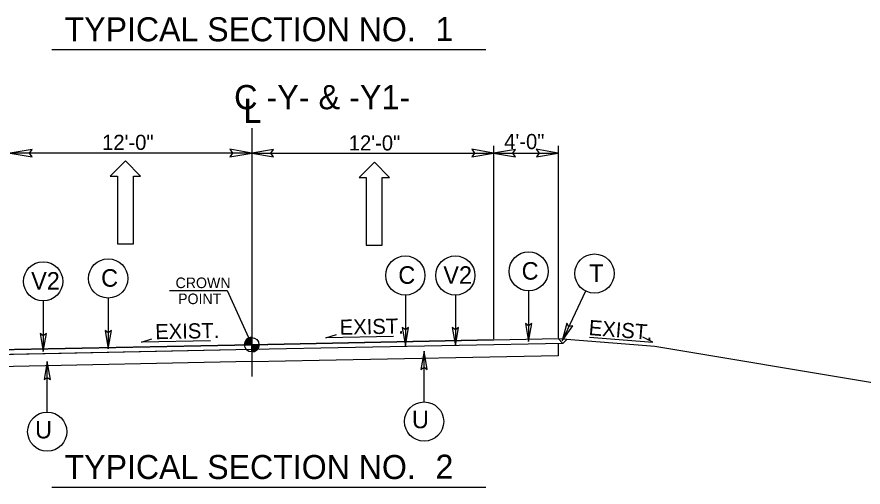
# Model space of a CAD drawing. Extents: x 2137858 to 2138172, y 2136084 to 2136289.
# Drawn here: x 2137980.7 to 2138065.4, y 2136135 to 2136182 of the extents above; entities that cross this region are included whole.
import ezdxf

# ---------------------------------------------------------------- set-up
doc = ezdxf.new("R2010")
doc.units = 0
for name, color, linetype in [('Old_Level_1', 7, 'Continuous'), ('Old_Level_11', 7, 'Continuous'), ('Old_Level_2', 7, 'Continuous'), ('Old_Level_20', 7, 'Continuous'), ('Old_Level_3', 7, 'Continuous'), ('Old_Level_4', 7, 'Continuous'), ('Typical Grade Point Symbol CELL', 7, 'Continuous')]:
    doc.layers.add(name, color=color, linetype=linetype)

msp = doc.modelspace()

# ---------------------------------------------------------------- linework, layer by layer
at = {"layer": 'Old_Level_1'}
for p, q in [((2137984.23, 2136178.793), (2138027.672, 2136178.793)), ((2138034.889, 2136149.88), (2138044.569, 2136149.106)), ((2138038.012, 2136150.024), (2138044.36, 2136149.517)), ((2138044.36, 2136149.517), (2138043.375, 2136150.009)), ((2138004.245, 2136148.772), (2137973.125, 2136148.15)), ((2138035.374, 2136149.395), (2138004.245, 2136148.772)), ((2138034.889, 2136149.385), (2138034.889, 2136148.185)), ((2138044.569, 2136149.106), (2138066.349, 2136145.476)), ((2138010.974, 2136147.705), (2138034.889, 2136148.185)), ((2138004.236, 2136147.57), (2137973.125, 2136146.95)), ((2138004.236, 2136147.57), (2138010.974, 2136147.705)), ((2137984.23, 2136135.034), (2138027.672, 2136135.034))]:
    msp.add_line(p, q, dxfattribs=at)
for points in [[(2138018.413, 2136150.094), (2138011.664, 2136149.954), (2138012.701, 2136150.3)], [(2138000.101, 2136149.652), (2137993.208, 2136149.509), (2137994.245, 2136149.856)]]:
    msp.add_lwpolyline(points, dxfattribs=at)
msp.add_lwpolyline([(2138004.236, 2136149.266), (2138034.889, 2136149.88), (2138035.374, 2136149.395), (2138004.245, 2136148.772), (2137973.629, 2136148.16), (2137973.125, 2136148.15), (2137973.629, 2136148.655)], close=True, dxfattribs=at)
at = {"layer": 'Old_Level_11'}
for p, q in [((2138004.236, 2136170.908), (2138004.236, 2136167.727)), ((2138028.436, 2136169.144), (2138028.436, 2136149.852)), ((2138034.889, 2136169.144), (2138034.889, 2136149.95)), ((2138004.236, 2136168.422), (2137980.082, 2136168.422)), ((2138004.236, 2136168.619), (2138004.236, 2136146.079)), ((2138004.236, 2136168.42), (2138028.436, 2136168.42)), ((2138028.436, 2136168.42), (2138034.889, 2136168.42)), ((2138031.941, 2136154.638), (2138031.941, 2136149.572)), ((2138037.64, 2136154.63), (2138035.283, 2136149.638)), ((2137989.872, 2136153.931), (2137989.872, 2136148.865)), ((2138019.605, 2136154.224), (2138019.605, 2136149.158)), ((2138024.607, 2136154.224), (2138024.607, 2136149.158)), ((2137983.371, 2136153.638), (2137983.371, 2136148.573)), ((2138021.482, 2136143.544), (2138021.482, 2136148.61)), ((2137983.781, 2136142.531), (2137983.781, 2136147.597))]:
    msp.add_line(p, q, dxfattribs=at)
for points in [[(2137982.26, 2136168.796), (2137980.082, 2136168.422), (2137982.273, 2136168.035), (2137981.994, 2136168.422)], [(2138002.058, 2136168.048), (2138004.236, 2136168.422), (2138002.045, 2136168.809), (2138002.324, 2136168.422)], [(2138006.414, 2136168.796), (2138004.236, 2136168.42), (2138006.425, 2136168.033), (2138006.147, 2136168.42)], [(2138026.258, 2136168.044), (2138028.436, 2136168.42), (2138026.246, 2136168.807), (2138026.524, 2136168.42)], [(2138030.614, 2136168.796), (2138028.436, 2136168.42), (2138030.626, 2136168.033), (2138030.347, 2136168.42)], [(2138032.711, 2136168.044), (2138034.889, 2136168.42), (2138032.698, 2136168.807), (2138032.977, 2136168.42)], [(2138031.628, 2136151.387), (2138031.941, 2136149.572), (2138032.264, 2136151.397), (2138031.941, 2136151.166)], [(2138035.771, 2136151.414), (2138035.283, 2136149.638), (2138036.351, 2136151.152), (2138035.961, 2136151.081)], [(2137983.058, 2136150.388), (2137983.371, 2136148.573), (2137983.693, 2136150.397), (2137983.371, 2136150.167)], [(2137989.559, 2136150.68), (2137989.872, 2136148.865), (2137990.195, 2136150.69), (2137989.872, 2136150.459)], [(2138019.292, 2136150.973), (2138019.605, 2136149.158), (2138019.927, 2136150.983), (2138019.605, 2136150.752)], [(2138024.294, 2136150.973), (2138024.607, 2136149.158), (2138024.93, 2136150.983), (2138024.607, 2136150.752)], [(2138021.795, 2136146.795), (2138021.482, 2136148.61), (2138021.159, 2136146.786), (2138021.482, 2136147.016)], [(2137984.094, 2136145.782), (2137983.781, 2136147.597), (2137983.458, 2136145.772), (2137983.781, 2136146.003)]]:
    msp.add_lwpolyline(points, close=True, dxfattribs=at)
for centre in [(2138019.605, 2136156.185), (2138024.608, 2136156.185), (2138031.942, 2136156.599), (2138038.527, 2136156.378), (2137983.371, 2136155.6), (2137989.873, 2136155.892), (2138021.48, 2136141.584), (2137983.779, 2136140.57)]:
    msp.add_circle(centre, 1.96, dxfattribs=at)
at = {"layer": 'Old_Level_2'}
for p, q in [((2138028.436, 2136149.751), (2138004.236, 2136149.267)), ((2138028.436, 2136149.751), (2138034.889, 2136149.88)), ((2138034.889, 2136149.88), (2138035.374, 2136149.395)), ((2138035.787, 2136149.808), (2138035.374, 2136149.395)), ((2138004.236, 2136149.266), (2137973.629, 2136148.655)), ((2138004.245, 2136148.772), (2138004.236, 2136149.266)), ((2138034.889, 2136148.652), (2138034.889, 2136148.159))]:
    msp.add_line(p, q, dxfattribs=at)
at = {"layer": 'Old_Level_3'}
for p, q in [((2137996.025, 2136154.67), (2138001.764, 2136154.67)), ((2138001.764, 2136154.67), (2138004.236, 2136149.266))]:
    msp.add_line(p, q, dxfattribs=at)
at = {"layer": 'Old_Level_4'}
for p, q in [((2137991.621, 2136167.635), (2137990.073, 2136166.11)), ((2137993.122, 2136166.11), (2137991.621, 2136167.635)), ((2138016.519, 2136167.503), (2138014.97, 2136165.978)), ((2138018.019, 2136165.978), (2138016.519, 2136167.503)), ((2137990.073, 2136166.11), (2137990.799, 2136166.11)), ((2137990.799, 2136166.11), (2137990.799, 2136159.334)), ((2137992.396, 2136159.334), (2137992.396, 2136166.11)), ((2137992.396, 2136166.11), (2137993.122, 2136166.11)), ((2138014.97, 2136165.978), (2138015.696, 2136165.978)), ((2138015.696, 2136165.978), (2138015.696, 2136159.202)), ((2138017.293, 2136159.202), (2138017.293, 2136165.978)), ((2138017.293, 2136165.978), (2138018.019, 2136165.978)), ((2137990.799, 2136159.334), (2137992.396, 2136159.334)), ((2138015.696, 2136159.202), (2138017.293, 2136159.202))]:
    msp.add_line(p, q, dxfattribs=at)
at = {"layer": 'Typical Grade Point Symbol CELL'}
for p, q in [((2138004.236, 2136149.266), (2138004.236, 2136149.992)), ((2138003.51, 2136149.266), (2138004.236, 2136149.266)), ((2138004.237, 2136148.54), (2138004.236, 2136149.266)), ((2138004.962, 2136149.266), (2138004.236, 2136149.266)), ((2138004.236, 2136149.266), (2138004.237, 2136148.54))]:
    msp.add_line(p, q, dxfattribs=at)
for points in [[(2138003.532, 2136149.443), (2138003.532, 2136149.266)], [(2138003.547, 2136149.493), (2138003.547, 2136149.266)], [(2138003.561, 2136149.533), (2138003.561, 2136149.266)], [(2138003.576, 2136149.567), (2138003.576, 2136149.266)], [(2138003.59, 2136149.598), (2138003.59, 2136149.266)], [(2138003.605, 2136149.624), (2138003.605, 2136149.266)], [(2138003.619, 2136149.648), (2138003.619, 2136149.266)], [(2138003.634, 2136149.671), (2138003.634, 2136149.266)], [(2138003.648, 2136149.692), (2138003.648, 2136149.266)], [(2138003.663, 2136149.711), (2138003.663, 2136149.266)], [(2138003.677, 2136149.729), (2138003.677, 2136149.266)], [(2138003.692, 2136149.746), (2138003.692, 2136149.266)], [(2138003.706, 2136149.763), (2138003.706, 2136149.266)], [(2138003.721, 2136149.777), (2138003.721, 2136149.266)], [(2138003.735, 2136149.792), (2138003.735, 2136149.266)], [(2138003.75, 2136149.805), (2138003.75, 2136149.266)], [(2138003.764, 2136149.817), (2138003.764, 2136149.266)], [(2138003.779, 2136149.83), (2138003.779, 2136149.266)], [(2138003.793, 2136149.842), (2138003.793, 2136149.266)], [(2138003.808, 2136149.851), (2138003.808, 2136149.266)], [(2138003.823, 2136149.863), (2138003.823, 2136149.266)], [(2138003.837, 2136149.872), (2138003.837, 2136149.266)], [(2138003.852, 2136149.882), (2138003.852, 2136149.266)], [(2138003.866, 2136149.89), (2138003.866, 2136149.266)], [(2138003.881, 2136149.898), (2138003.881, 2136149.266)], [(2138003.895, 2136149.906), (2138003.895, 2136149.266)], [(2138003.91, 2136149.914), (2138003.91, 2136149.266)], [(2138003.924, 2136149.921), (2138003.924, 2136149.266)], [(2138003.939, 2136149.927), (2138003.939, 2136149.266)], [(2138003.953, 2136149.934), (2138003.953, 2136149.266)], [(2138003.968, 2136149.94), (2138003.968, 2136149.266)], [(2138003.982, 2136149.946), (2138003.982, 2136149.266)], [(2138003.997, 2136149.951), (2138003.997, 2136149.266)], [(2138004.011, 2136149.956), (2138004.011, 2136149.266)], [(2138004.026, 2136149.961), (2138004.026, 2136149.266)], [(2138004.04, 2136149.964), (2138004.04, 2136149.266)], [(2138004.055, 2136149.969), (2138004.055, 2136149.266)], [(2138004.069, 2136149.972), (2138004.069, 2136149.266)], [(2138004.084, 2136149.976), (2138004.084, 2136149.266)], [(2138004.098, 2136149.979), (2138004.098, 2136149.266)], [(2138004.113, 2136149.982), (2138004.113, 2136149.266)], [(2138004.127, 2136149.984), (2138004.127, 2136149.266)], [(2138004.142, 2136149.985), (2138004.142, 2136149.266)], [(2138004.156, 2136149.987), (2138004.156, 2136149.266)], [(2138004.171, 2136149.988), (2138004.171, 2136149.266)], [(2138004.186, 2136149.99), (2138004.186, 2136149.266)], [(2138004.2, 2136149.99), (2138004.2, 2136149.266)], [(2138004.215, 2136149.992), (2138004.215, 2136149.266)], [(2138004.229, 2136149.992), (2138004.229, 2136149.992), (2138004.229, 2136149.266)], [(2138003.518, 2136149.369), (2138003.518, 2136149.266)], [(2138004.247, 2136149.266), (2138004.247, 2136148.54), (2138004.247, 2136148.54)], [(2138004.261, 2136149.266), (2138004.261, 2136148.54)], [(2138004.276, 2136149.266), (2138004.276, 2136148.541)], [(2138004.29, 2136149.266), (2138004.29, 2136148.541)], [(2138004.305, 2136149.266), (2138004.305, 2136148.543)], [(2138004.319, 2136149.266), (2138004.319, 2136148.544)], [(2138004.334, 2136149.266), (2138004.334, 2136148.546)], [(2138004.348, 2136149.266), (2138004.348, 2136148.549)], [(2138004.363, 2136149.266), (2138004.363, 2136148.551)], [(2138004.378, 2136149.266), (2138004.378, 2136148.554)], [(2138004.392, 2136149.266), (2138004.392, 2136148.557)], [(2138004.407, 2136149.266), (2138004.407, 2136148.561)], [(2138004.421, 2136149.266), (2138004.421, 2136148.564)], [(2138004.436, 2136149.266), (2138004.436, 2136148.569)], [(2138004.45, 2136149.266), (2138004.45, 2136148.572)], [(2138004.465, 2136149.266), (2138004.465, 2136148.577)], [(2138004.479, 2136149.266), (2138004.479, 2136148.582)], [(2138004.494, 2136149.266), (2138004.494, 2136148.586)], [(2138004.508, 2136149.266), (2138004.508, 2136148.593)], [(2138004.523, 2136149.266), (2138004.523, 2136148.599)], [(2138004.537, 2136149.266), (2138004.537, 2136148.606)], [(2138004.552, 2136149.266), (2138004.552, 2136148.612)], [(2138004.566, 2136149.266), (2138004.566, 2136148.619)], [(2138004.581, 2136149.266), (2138004.581, 2136148.627)], [(2138004.595, 2136149.266), (2138004.595, 2136148.635)], [(2138004.61, 2136149.266), (2138004.61, 2136148.643)], [(2138004.624, 2136149.266), (2138004.624, 2136148.653)], [(2138004.639, 2136149.266), (2138004.639, 2136148.662)], [(2138004.653, 2136149.266), (2138004.653, 2136148.672)], [(2138004.668, 2136149.266), (2138004.668, 2136148.682)], [(2138004.682, 2136149.266), (2138004.682, 2136148.693)], [(2138004.697, 2136149.266), (2138004.697, 2136148.704)], [(2138004.711, 2136149.266), (2138004.711, 2136148.717)], [(2138004.726, 2136149.266), (2138004.726, 2136148.73)], [(2138004.741, 2136149.266), (2138004.741, 2136148.743)], [(2138004.755, 2136149.266), (2138004.755, 2136148.757)], [(2138004.77, 2136149.266), (2138004.77, 2136148.774)], [(2138004.784, 2136149.266), (2138004.784, 2136148.79)], [(2138004.799, 2136149.266), (2138004.799, 2136148.807)], [(2138004.813, 2136149.266), (2138004.813, 2136148.825)], [(2138004.828, 2136149.266), (2138004.828, 2136148.845)], [(2138004.842, 2136149.266), (2138004.842, 2136148.866)], [(2138004.857, 2136149.266), (2138004.857, 2136148.888)], [(2138004.871, 2136149.266), (2138004.871, 2136148.914)], [(2138004.886, 2136149.266), (2138004.886, 2136148.941)], [(2138004.9, 2136149.266), (2138004.9, 2136148.972)], [(2138004.915, 2136149.266), (2138004.915, 2136149.006)], [(2138004.929, 2136149.266), (2138004.929, 2136149.049)], [(2138004.944, 2136149.266), (2138004.944, 2136149.101)], [(2138004.958, 2136149.266), (2138004.958, 2136149.187)]]:
    msp.add_lwpolyline(points, dxfattribs=at)
msp.add_circle((2138004.237, 2136149.266), 0.726, dxfattribs=at)
for start, end in [(90.00952, 180.00952), (270.00952, 0.00952)]:
    msp.add_arc((2138004.237, 2136149.266), 0.726, start, end, dxfattribs=at)

# ---------------------------------------------------------------- texts
at = {"layer": 'Old_Level_1'}
for s, p in [('12\'-0"', (2137989.267, 2136168.739)), ('12\'-0"', (2138013.941, 2136168.681)), ('4\'-0"', (2138029.491, 2136168.818))]:
    msp.add_text(s, height=1.5125, dxfattribs=at).set_placement(p)
for rotation, p in [(1.19158, (2137994.598, 2136149.811)), (1.19158, (2138013.054, 2136150.256)), (355.42832, (2138037.908, 2136150.239))]:
    msp.add_text('EXIST.', height=1.5125, rotation=rotation, dxfattribs=at).set_placement(p)
at = {"layer": 'Old_Level_11'}
for s, p in [('CROWN', (2137996.616, 2136154.924)), ('POINT', (2137996.871, 2136153.32))]:
    msp.add_text(s, height=1.0583, dxfattribs=at).set_placement(p)
at = {"layer": 'Old_Level_20'}
for s, height, p in [('C', 1.754, (2138018.902, 2136155.355)), ('V2', 1.7545, (2138023.405, 2136155.355)), ('C', 1.754, (2138031.239, 2136155.769)), ('T', 1.754, (2138038.007, 2136155.548)), ('V2', 1.7545, (2137982.168, 2136154.769)), ('C', 1.754, (2137989.17, 2136155.062)), ('U', 1.754, (2138020.266, 2136140.913)), ('U', 1.754, (2137982.564, 2136139.899))]:
    msp.add_text(s, height=height, dxfattribs=at).set_placement(p)
at = {"layer": 'Old_Level_3'}
for s, height, p in [('TYPICAL SECTION NO.  ', 2.4, (2137985.518, 2136179.597)), ('1', 2.4, (2138022.622, 2136179.629)), ('C -Y- & -Y1-', 2.42, (2138002.474, 2136172.806)), ('L', 2.42, (2138003.414, 2136171.446)), ('TYPICAL SECTION NO.  ', 2.4, (2137985.518, 2136135.838)), ('2', 2.4, (2138022.622, 2136135.87))]:
    msp.add_text(s, height=height, dxfattribs=at).set_placement(p)

doc.saveas('drawing.dxf')
